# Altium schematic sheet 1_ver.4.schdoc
size 302 x 215 mm; Name: A_A4; Symbol: A_A4; Device: A_A4; @Project Name: VisionGuard; REV: 4; Date: 2025-06-20; Sheet: 1/2; Draw By: Soha Saleh; Company: NXU; Convert to PCB: yes; Add into BOM: yes; spicePre: .; @Page No: 1; @Page Count: 2; @Schematic Name: eye-protect_3; @Board Name: eye-protect_3; @Update Date: 2025-07-23; @Create Time: 04:59:38; @Update Time: 05:29:28; @Page Name: ver.4; @Create Date: 2025-07-19
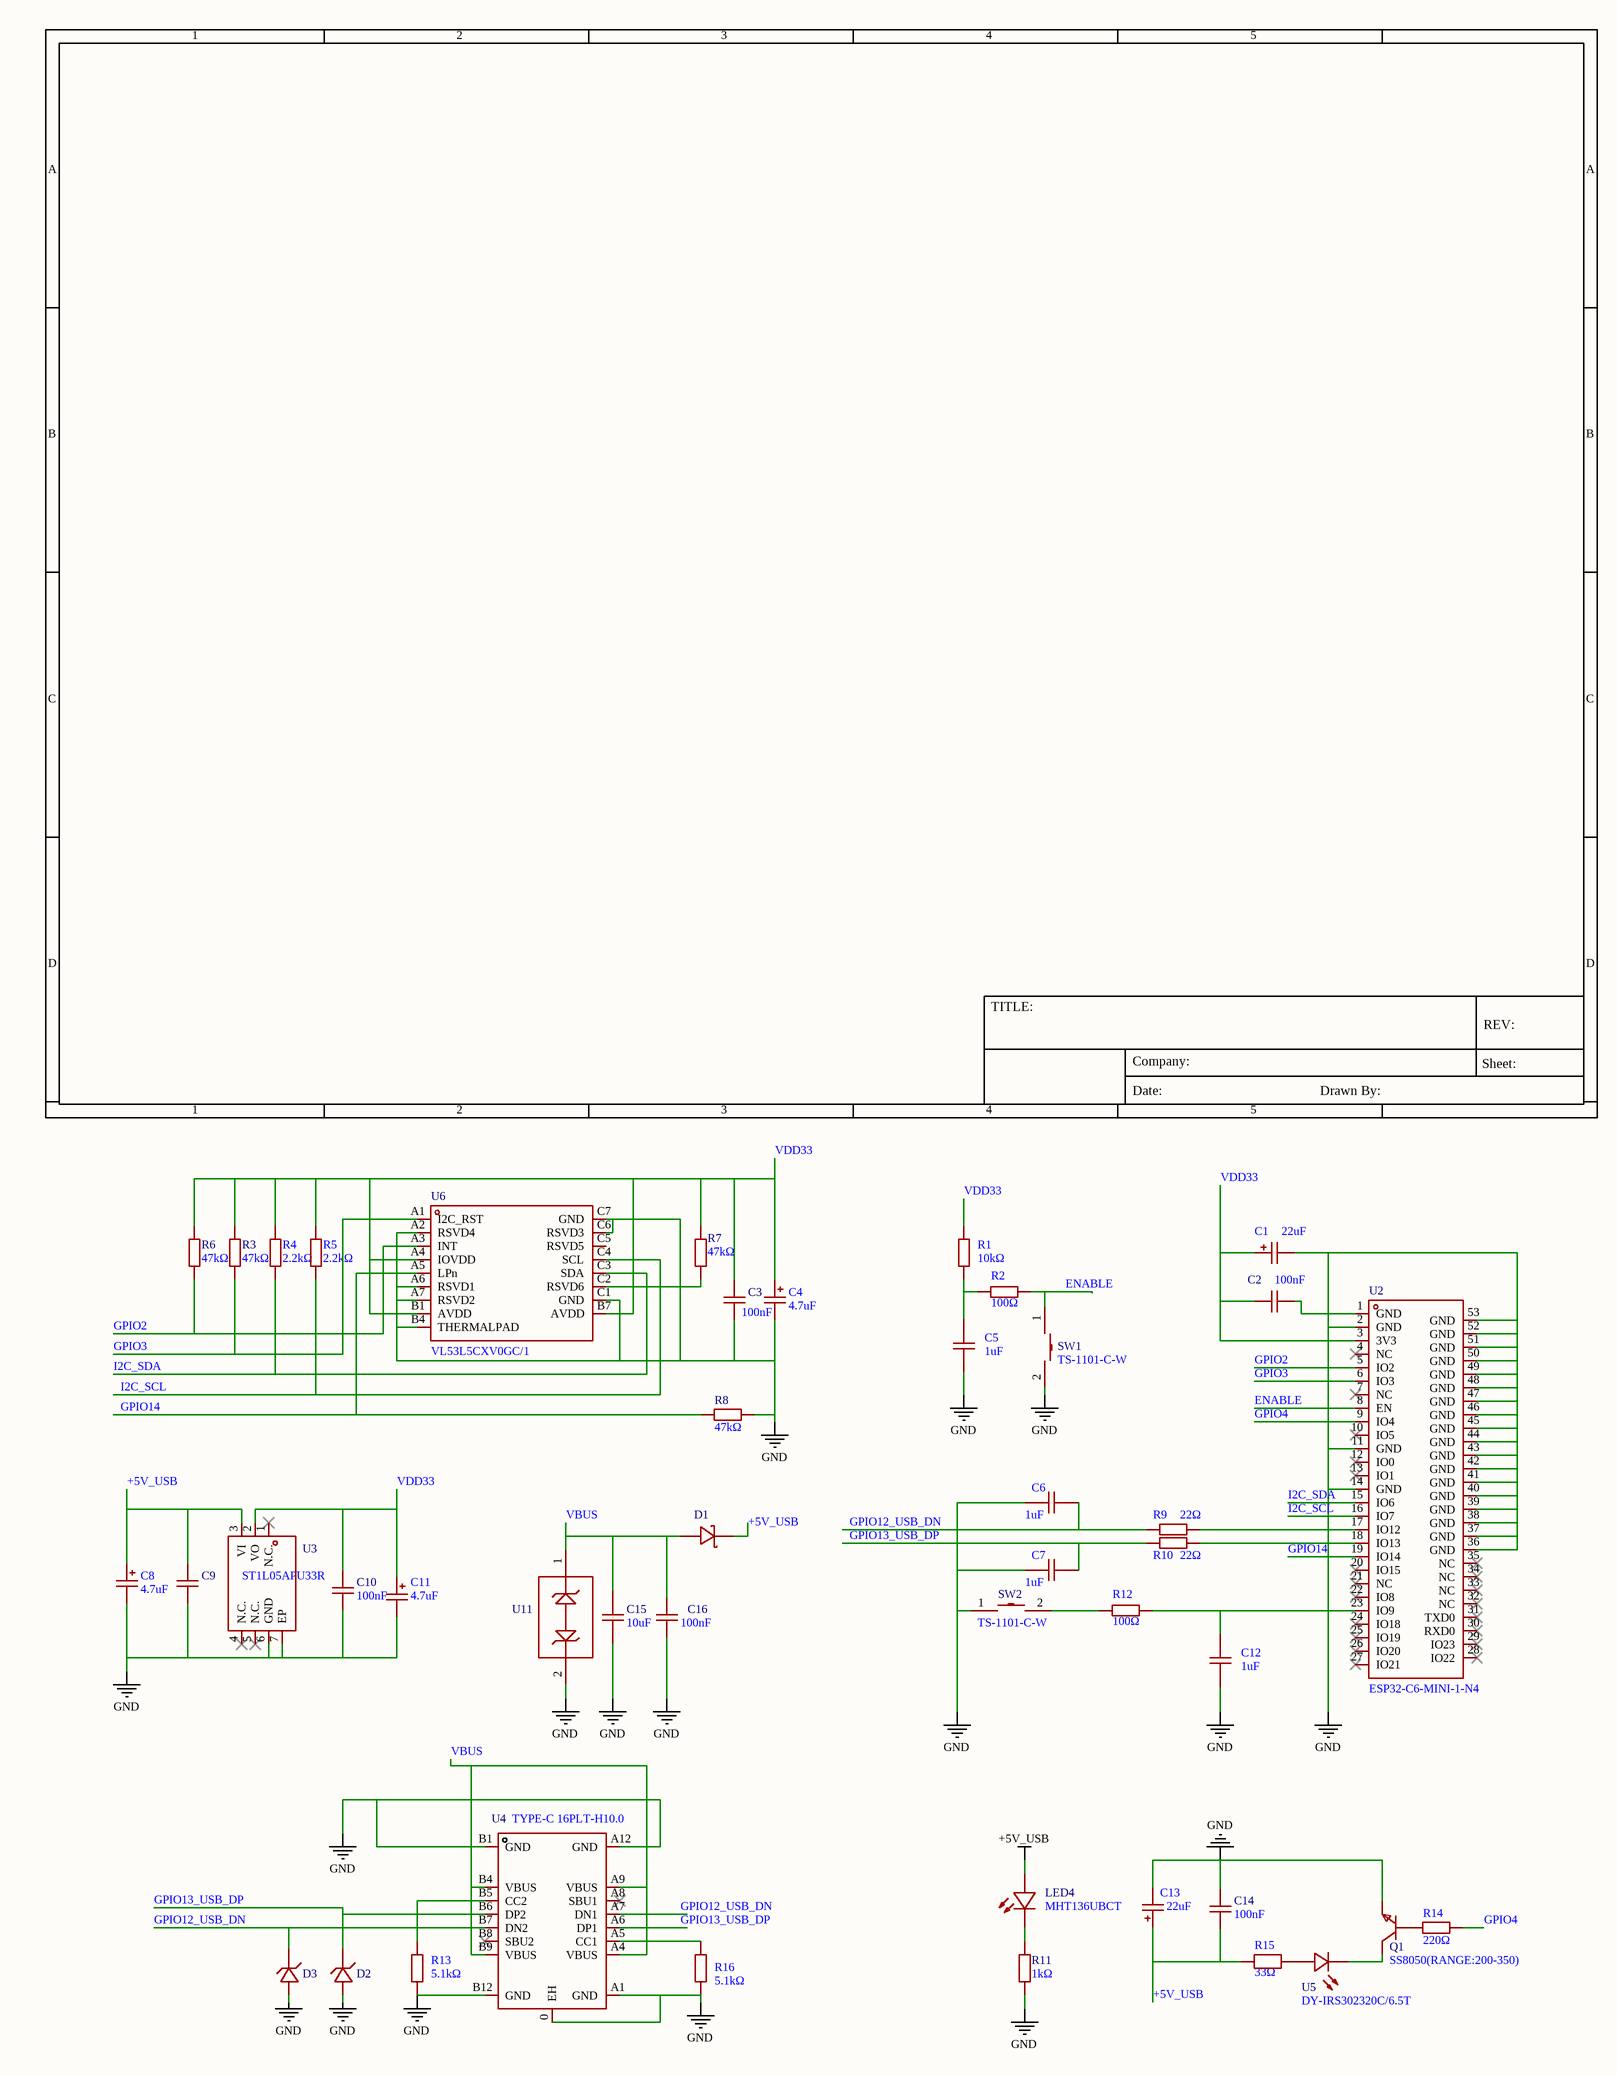
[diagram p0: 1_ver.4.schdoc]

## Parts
C1  22uF  [CASE-A_3216]
C2  100nF  [C0402]
C3  100nF  [C0402]
C4  4.7uF  [CAP-SMD_L2.0-W1.3-FD]
C5  1uF  [C0603]
C6  1uF  [C0603]
C7  1uF  [C0603]
C8  4.7uF  [CAP-SMD_L2.0-W1.3-FD]
C9  100nF  [C0402]  (value not drawn)
C10  100nF  [C0402]
C11  4.7uF  [CAP-SMD_L2.0-W1.3-FD]
C12  1uF  [C0603]
C13  22uF  [CASE-A_3216]
C14  100nF  [C0402]
C15  10uF  [C0805]
C16  100nF  [C0402]
D1  BAT60A E6327  [SOD-323_L1.8-W1.3-LS2.5-RD]  (value not drawn)
D2  TPD1E05U06DPYR  [X2SON-2_L1.0-W0.6-P0.70-RD]  (value not drawn)
D3  TPD1E05U06DPYR  [X2SON-2_L1.0-W0.6-P0.70-RD]  (value not drawn)
LED4  MHT136UBCT  [LED0402-RD_BLUE]
Q1  SS8050(RANGE:200-350)  [SOT-23-3_L2.9-W1.3-P1.90-LS2.4-BR]
R1  10kΩ  [R0603]
R2  100Ω  [R0603]
R3  47kΩ  [R0402]
R4  2.2kΩ  [R0603]
R5  2.2kΩ  [R0603]
R6  47kΩ  [R0402]
R7  47kΩ  [R0402]
R8  47kΩ  [R0402]
R9  22Ω  [R0603]
R10  22Ω  [R0603]
R11  1kΩ  [R0402]
R12  100Ω  [R0603]
R13  5.1kΩ  [R0603]
R14  220Ω  [R0603]
R15  33Ω  [R1206]
R16  5.1kΩ  [R0603]
SW1  TS-1101-C-W  [SW-SMD_L6.0-W3.3-LS8.0]
SW2  TS-1101-C-W  [SW-SMD_L6.0-W3.3-LS8.0]
U2  ESP32-C6-MINI-1-N4  [WIFIM-SMD_61P-L16.6-W13.2-P0.80-ESP32-C6-MINI-1-N4]
U3  ST1L05APU33R  [DFN-6_L3.0-W3.0-P0.95-BL-EP-1]
U4  TYPE-C 16PLT-H10.0  [TYPE-C-SMD_USB4120-03-C]
U5  DY-IRS302320C/6.5T  [LED-SMD_L3.0-W2.0-R-RD]
U6  VL53L5CXV0GC/1  [LGA-16_L6.4-W3.0_VL53L5CXV0GC-1]
U11  TPD1E10B06DPYR  [X1SON-2_L1.0-W0.6-P0.65-BI]  (value not drawn)

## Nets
+5V_USB: C8.1 C9.1 C13.1 C14.2 D1.1(C) LED4.2(A) R15.1 U3.3(VI)
GND: C1.2 C2.1 C3.2 C4.2 C5.2 C6.2 C7.2 C8.2 C9.2 C10.2 C11.2 C12.2 C13.2 C14.1 C15.2 C16.2 D2.2(GND) D3.2(GND) Q1.2(E) R8.1 R9.2 R11.2 R13.2 R16.2 SW1.2 SW2.1 U2.1(GND) U2.2(GND) U2.11(GND) U2.14(GND) U2.17(IO12) U2.36(GND) U2.37(GND) U2.38(GND) U2.39(GND) U2.40(GND) U2.41(GND) U2.42(GND) U2.43(GND) U2.44(GND) U2.45(GND) U2.46(GND) U2.47(GND) U2.48(GND) U2.49(GND) U2.50(GND) U2.51(GND) U2.52(GND) U2.53(GND) U3.6(GND) U3.7(EP) U4.0(EH) U4.A1(GND) U4.A12(GND) U4.B1(GND) U4.B12(GND) U6.A2(RSVD4) U6.A6(RSVD1) U6.A7(RSVD2) U6.B4(THERMALPAD) U6.C1(GND) U6.C6(RSVD3) U6.C7(GND) U11.2
ENABLE: R2.2 SW1.1 U2.8(EN)
GPIO2: R6.1 U2.5(IO2) U6.A3(INT)
GPIO3: R3.1 U2.6(IO3) U6.A1(I2C_RST)
GPIO4: R14.1 U2.9(IO4)
GPIO12_USB_DN: C6.1 D3.1(I/O) R9.1 U4.A7(DN1) U4.B7(DN2)
GPIO13_USB_DP: C7.1 D2.1(I/O) R10.1 U4.A6(DP1) U4.B6(DP2)
GPIO14: R8.2 U2.19(IO14) U6.A5(LPn)
I2C_SCL: R5.1 U2.16(IO7) U6.C4(SCL)
I2C_SDA: R4.1 U2.15(IO6) U6.C3(SDA)
VBUS: C15.1 C16.1 D1.2(A) U4.A4(VBUS) U4.A9(VBUS) U4.B4(VBUS) U4.B9(VBUS) U11.1
VDD33: C1.1 C2.2 C3.1 C4.1 C10.1 C11.1 R1.2 R3.2 R4.2 R5.2 R6.2 R7.2 U2.3(3V3) U3.2(VO) U6.A4(IOVDD) U6.B1(AVDD) U6.B7(AVDD)
NetC5_1: C5.1 R1.1 R2.1
NetC12_1: C12.1 R12.2 U2.23(IO9)
NetLED4_1: LED4.1(K) R11.1
NetQ1_1: Q1.1(B) R14.2
NetQ1_3: Q1.3(C) U5.2(-)
NetR7_1: R7.1 U6.C2(RSVD6)
NetR10_2: R10.2 U2.18(IO13)
NetR12_1: R12.1 SW2.2
NetR13_1: R13.1 U4.B5(CC2)
NetR15_2: R15.2 U5.1(+)
NetR16_1: R16.1 U4.A5(CC1)

Not connected (* = marked no-connect by the designer): U2 4(NC)* 7(NC)* 10(IO5)* 12(IO0)* 13(IO1)* 20(IO15)* 21(NC)* 22(IO8)* 24(IO18)* 25(IO19)* 26(IO20)* 27(IO21)* 28(IO22)* 29(IO23)* 30(RXD0)* 31(TXD0)* 32(NC)* 33(NC)* 34(NC)* 35(NC)*; U3 1(N.C.)* 4(N.C.)* 5(N.C.)*; U4 A8(SBU1)* B8(SBU2)*; U6 C5(RSVD5)

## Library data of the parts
C1 C13 = TAJA226K010RNJ: Manufacturer: Kyocera AVX; Add into BOM: yes; Tolerance: ±10%; Voltage Rating: 10V; Equivalent Series Resistance(ESR): 3Ω@100kHz
C2 C3 C9 C10 C14 C16 = CL05B104KA5NNNC: Manufacturer: SAMSUNG(三星); Add into BOM: yes; Tolerance: ±10%
C4 C8 C11 = TAJR475K010RNJ: Manufacturer: Kyocera AVX; Add into BOM: yes; Tolerance: ±10%; Equivalent Series Resistance(ESR): 9Ω@100kHz
C5-C7 C12 = CL10A105KB8NNNC: Manufacturer: SAMSUNG(三星); Symbol: CAP; Add into BOM: yes; Tolerance: ±10%; Check: true
C15 = GRM21BZ71E106KE15L: Manufacturer: muRata(村田); Add into BOM: yes; Tolerance: ±10%
D1 = BAT60A E6327: Manufacturer: Infineon(英飞凌); Symbol: BAT60AE6327H; Add into BOM: yes; Diode Configuration: Single; Forward Voltage (Vf@If): 300mV@1A; Reverse Voltage (Vr): 10V; Average Rectified Current (Io): 3A; Reverse Leakage Current (Ir): 600uA@8V
D2 D3 = TPD1E05U06DPYR: Manufacturer: TI(德州仪器); Add into BOM: yes; Reverse Stand-Off Voltage (Vrwm): 5.5V@Max; Maximum Clamping Voltage: 14V; Peak Pulse Current (Ipp)@10/1000us: 2.5A@8/20us; Breakdown Voltage: 6V; Type: TVS
LED4 = MHT136UBCT: Manufacturer: MEIHUA(美华); Add into BOM: yes; Emitted Color: Blue; Power Dissipation: 95mW; Forward Current: 5mA; Dominant Wavelength: 460nm~475nm; Peak Wavelength: 468nm; Lens Color: 无色透明透镜; Viewing Angle: 120°
Q1 = SS8050(RANGE:200-350)_C2150: Manufacturer: CJ(江苏长电/长晶); Symbol: SS8050_C2150; Add into BOM: yes; DC Current Gain (hFE@Ic,Vce): 200@800mA,1V; Transition Frequency (fT): 100MHz; Collector Cut-Off Current (Icbo): 100nA; Collector-Emitter Saturation Voltage (VCE(sat)@Ic,Ib): 500mV@800mA,80mA; Check: true
R1 = 0603WAF1002T5E: Manufacturer: UNI-ROYAL(厚声); Symbol: Res; Add into BOM: yes; Tolerance: ±1%; Power(Watts): 100mW; Voltage-Supply(Max): 75V; Temperature Coefficient: ±100ppm/℃; Check: true
R2 R12 = 0603WAF1000T5E: Manufacturer: UNI-ROYAL(厚声); Symbol: Res; Add into BOM: yes; Tolerance: ±1%; Temperature Coefficient: ±200ppm/℃; Check: true
R3 R6-R8 = 0402WGF4702TCE: Manufacturer: UNI-ROYAL(厚声); Add into BOM: yes; Tolerance: ±1%; Temperature Coefficient: ±100ppm/℃
R4 R5 = 0603WAF2201T5E_C4190: Manufacturer: UNI-ROYAL(厚声); Symbol: Res; Add into BOM: yes; Tolerance: ±1%; Temperature Coefficient: ±100ppm/℃; Check: true
R9 R10 = 0603WAF220JT5E: Manufacturer: UNI-ROYAL(厚声); Symbol: Res; Add into BOM: yes; Tolerance: ±1%; Temperature Coefficient: ±100ppm/℃; Check: true
R11 = ERJ2RKF1001X_C242161: Manufacturer: PANASONIC(松下); Add into BOM: yes; Tolerance: ±1%; Temperature Coefficient: ±100ppm/℃
R13 R16 = 0603WAF5101T5E: Manufacturer: UNI-ROYAL(厚声); Symbol: Res; Add into BOM: yes; Tolerance: ±1%; Temperature Coefficient: ±100ppm/℃; Check: true
R14 = 0603WAF2200T5E: Manufacturer: UNI-ROYAL(厚声); Symbol: Res; Add into BOM: yes; Tolerance: ±1%; Temperature Coefficient: ±100ppm/℃; Check: true
R15 = AS0606J0330T5E_C966057: Manufacturer: UNI-ROYAL(厚声); Symbol: AS06W2J0330T5E; Add into BOM: yes; Tolerance: ±5%; Temperature Coefficient: ±100ppm/℃
SW1 SW2 = TS-1101-C-W: Manufacturer: XKB Connectivity(中国星坤); Add into BOM: yes; Circuit: SPST; Actuator Style: Rectangle button; Operating Force: 260gf; Switch Length: 6mm; Switch Width: 3.6mm; Switch Height: 2.5mm; Strike Gundam: 不带; Contact Current: 50mA; Voltage Rating (DC): 12V; Actuator/Cap Color: 白色带淡绿; With Lamp: No; Mechanical Life: 5万次; Check: true
U2 = ESP32-C6-MINI-1-N4: Manufacturer: ESPRESSIF(乐鑫); Add into BOM: yes; Check: true
U3 = ST1L05APU33R: Manufacturer: ST(意法半导体); Add into BOM: yes; Output Type: Fixed; Maximum Input Voltage: 7V; Output Voltage: 3.3V; Output Current: 1.3A; Power Supply Rejection Ratio (PSRR): 65dB@(120Hz); Dropout Voltage: 500mV@(1.3A); standby current: 650uA; Output Polarity: Positive electrode; Number of Outputs: 1
U4 = TYPE-C 16PLT-H10.0: Manufacturer: SHOU HAN(首韩); Add into BOM: yes; Gender: Female; Number of Contacts: 16P; Number of Ports: 1; Current Rating - Power (Max): 5A; Rated Voltage (Max): 20V; Connect-Disconnect Life: 10,000 times; Core Colour: Black
U5 = DY-IRS302320C/6.5T: Manufacturer: TONYU(东裕); Add into BOM: yes; Vf - Forward Voltage: 1.3V~2V; Power Dissipation: 150mW; Wavelength: 940nm; Radiant Intensity: 150mW/sr; Current - DC Forward (If): 100mA; Reverse Voltage: 5V; View Angle: 35°; Check: true
U6 = VL53L5CXV0GC/1: Manufacturer: ST(意法半导体); Add into BOM: yes; Supply Voltage: 2.8V~3.3V; Iinearity Range: 4m
U11 = TPD1E10B06DPYR_C48260: Manufacturer: TI(德州仪器); Add into BOM: yes; Reverse Stand-Off Voltage (Vrwm): 5.5V@Max; Maximum Clamping Voltage: 14V; Peak Pulse Power Dissipation (Ppp)@10/1000us: 90W; Breakdown Voltage: 6V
